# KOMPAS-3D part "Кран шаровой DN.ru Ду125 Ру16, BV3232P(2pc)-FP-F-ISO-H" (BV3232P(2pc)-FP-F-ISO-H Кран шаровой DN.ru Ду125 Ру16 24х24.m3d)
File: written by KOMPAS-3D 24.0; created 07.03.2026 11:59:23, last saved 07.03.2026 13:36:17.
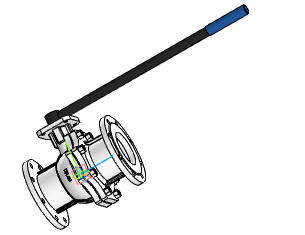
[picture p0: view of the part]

Document properties: Автор: R2D2; Полное имя файла: E:\Работа\Зайцев\BV3232P(2pc)-FP-F-ISO-H Кран шаровой DN.ru Ду15-300 Ру16-40\DN125 PN16 24х24\BV3232P(2pc)-FP-F-ISO-H Кран шаровой DN.ru Ду125 Ру16 24х24.m3d

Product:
- Part/product: Кран шаровой DN.ru Ду125 Ру16  | designation BV3232P(2pc)-FP-F-ISO-H
    Масса: 32
    Раздел спецификации: Прочие изделия
    Примечание: D160-74641

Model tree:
1. Операция без истории:1

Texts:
  BV3232P(2pc)-FP-F-ISO-H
